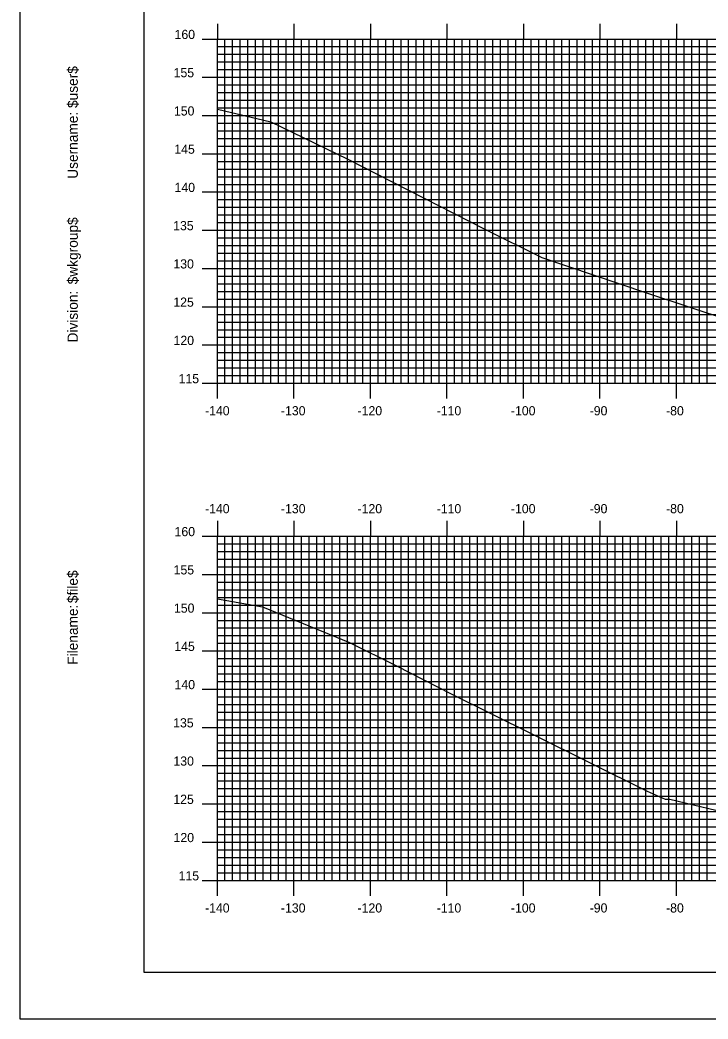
# Model space of a CAD drawing. Extents: x 851533 to 851876, y 366605 to 366825.
# Drawn here: x 851532.7 to 851622.6, y 366604.9 to 366735.5 of the extents above; entities that cross this region are included whole.
import ezdxf

# ---------------------------------------------------------------- set-up
doc = ezdxf.new("R2010")
doc.units = 0
for name, color, linetype in [('BORDER', 7, 'Continuous'), ('H_V ANNOTATION', 7, 'Continuous'), ('MAJOR', 7, 'Continuous'), ('MINOR', 7, 'Continuous'), ('PLOT BOUNDARY', 7, 'Continuous'), ('S_Roadway_Centerline', 7, 'Continuous')]:
    doc.layers.add(name, color=color, linetype=linetype)

msp = doc.modelspace()

# ---------------------------------------------------------------- linework, layer by layer
at = {"layer": 'BORDER'}
msp.add_lwpolyline([(851548.85, 366611.06), (851868.85, 366611.06), (851868.85, 366821.06), (851548.85, 366821.06)], close=True, dxfattribs=at)
at = {"layer": 'MAJOR'}
for p, q in [((851558.45, 366735.06), (851558.45, 366733.06)), ((851568.45, 366735.06), (851568.45, 366733.06)), ((851578.45, 366735.06), (851578.45, 366733.06)), ((851588.45, 366735.06), (851588.45, 366733.06)), ((851598.45, 366735.06), (851598.45, 366733.06)), ((851608.45, 366735.06), (851608.45, 366733.06)), ((851618.45, 366735.06), (851618.45, 366733.06)), ((851556.45, 366733.06), (851558.45, 366733.06)), ((851558.45, 366733.06), (851838.45, 366733.06)), ((851558.45, 366688.06), (851558.45, 366733.06)), ((851558.45, 366688.06), (851558.45, 366733.06)), ((851558.45, 366733.06), (851838.45, 366733.06)), ((851568.45, 366688.06), (851568.45, 366733.06)), ((851578.45, 366688.06), (851578.45, 366733.06)), ((851588.45, 366688.06), (851588.45, 366733.06)), ((851598.45, 366688.06), (851598.45, 366733.06)), ((851608.45, 366688.06), (851608.45, 366733.06)), ((851618.45, 366688.06), (851618.45, 366733.06)), ((851556.45, 366728.06), (851558.45, 366728.06)), ((851558.45, 366728.06), (851838.45, 366728.06)), ((851556.45, 366723.06), (851558.45, 366723.06)), ((851558.45, 366723.06), (851838.45, 366723.06)), ((851556.45, 366718.06), (851558.45, 366718.06)), ((851558.45, 366718.06), (851838.45, 366718.06)), ((851556.45, 366713.06), (851558.45, 366713.06)), ((851558.45, 366713.06), (851838.45, 366713.06)), ((851556.45, 366708.06), (851558.45, 366708.06)), ((851558.45, 366708.06), (851838.45, 366708.06)), ((851556.45, 366703.06), (851558.45, 366703.06)), ((851558.45, 366703.06), (851838.45, 366703.06)), ((851556.45, 366698.06), (851558.45, 366698.06)), ((851558.45, 366698.06), (851838.45, 366698.06)), ((851556.45, 366693.06), (851558.45, 366693.06)), ((851558.45, 366693.06), (851838.45, 366693.06)), ((851556.45, 366688.06), (851558.45, 366688.06)), ((851558.45, 366688.06), (851838.45, 366688.06)), ((851558.45, 366688.06), (851838.45, 366688.06)), ((851558.45, 366686.05), (851558.45, 366688.06)), ((851568.45, 366686.05), (851568.45, 366688.06)), ((851578.45, 366686.05), (851578.45, 366688.06)), ((851588.45, 366686.05), (851588.45, 366688.06)), ((851598.45, 366686.05), (851598.45, 366688.06)), ((851608.45, 366686.05), (851608.45, 366688.06)), ((851618.45, 366686.05), (851618.45, 366688.06)), ((851558.45, 366670.06), (851558.45, 366668.06)), ((851568.45, 366670.06), (851568.45, 366668.06)), ((851578.45, 366670.06), (851578.45, 366668.06)), ((851588.45, 366670.06), (851588.45, 366668.06)), ((851598.45, 366670.06), (851598.45, 366668.06)), ((851608.45, 366670.06), (851608.45, 366668.06)), ((851618.45, 366670.06), (851618.45, 366668.06)), ((851556.45, 366668.06), (851558.45, 366668.06)), ((851558.45, 366668.06), (851838.45, 366668.06)), ((851558.45, 366623.06), (851558.45, 366668.06)), ((851558.45, 366623.06), (851558.45, 366668.06)), ((851558.45, 366668.06), (851838.45, 366668.06)), ((851568.45, 366623.06), (851568.45, 366668.06)), ((851578.45, 366623.06), (851578.45, 366668.06)), ((851588.45, 366623.06), (851588.45, 366668.06)), ((851598.45, 366623.06), (851598.45, 366668.06)), ((851608.45, 366623.06), (851608.45, 366668.06)), ((851618.45, 366623.06), (851618.45, 366668.06)), ((851556.45, 366663.06), (851558.45, 366663.06)), ((851558.45, 366663.06), (851838.45, 366663.06)), ((851556.45, 366658.06), (851558.45, 366658.06)), ((851558.45, 366658.06), (851838.45, 366658.06)), ((851556.45, 366653.06), (851558.45, 366653.06)), ((851558.45, 366653.06), (851838.45, 366653.06)), ((851556.45, 366648.06), (851558.45, 366648.06)), ((851558.45, 366648.06), (851838.45, 366648.06)), ((851556.45, 366643.06), (851558.45, 366643.06)), ((851558.45, 366643.06), (851838.45, 366643.06)), ((851556.45, 366638.06), (851558.45, 366638.06)), ((851558.45, 366638.06), (851838.45, 366638.06)), ((851556.45, 366633.06), (851558.45, 366633.06)), ((851558.45, 366633.06), (851838.45, 366633.06)), ((851556.45, 366628.06), (851558.45, 366628.06)), ((851558.45, 366628.06), (851838.45, 366628.06)), ((851556.45, 366623.06), (851558.45, 366623.06)), ((851558.45, 366623.06), (851838.45, 366623.06)), ((851558.45, 366623.06), (851838.45, 366623.06)), ((851558.45, 366621.05), (851558.45, 366623.06)), ((851568.45, 366621.05), (851568.45, 366623.06)), ((851578.45, 366621.05), (851578.45, 366623.06)), ((851588.45, 366621.05), (851588.45, 366623.06)), ((851598.45, 366621.05), (851598.45, 366623.06)), ((851608.45, 366621.05), (851608.45, 366623.06)), ((851618.45, 366621.05), (851618.45, 366623.06))]:
    msp.add_line(p, q, dxfattribs=at)
at = {"layer": 'MINOR'}
for p, q in [((851559.45, 366688.06), (851559.45, 366733.06)), ((851560.45, 366688.06), (851560.45, 366733.06)), ((851561.45, 366688.06), (851561.45, 366733.06)), ((851562.45, 366688.06), (851562.45, 366733.06)), ((851563.45, 366688.06), (851563.45, 366733.06)), ((851564.45, 366688.06), (851564.45, 366733.06)), ((851565.45, 366688.06), (851565.45, 366733.06)), ((851566.45, 366688.06), (851566.45, 366733.06)), ((851567.45, 366688.06), (851567.45, 366733.06)), ((851569.45, 366688.06), (851569.45, 366733.06)), ((851570.45, 366688.06), (851570.45, 366733.06)), ((851571.45, 366688.06), (851571.45, 366733.06)), ((851572.45, 366688.06), (851572.45, 366733.06)), ((851573.45, 366688.06), (851573.45, 366733.06)), ((851574.45, 366688.06), (851574.45, 366733.06)), ((851575.45, 366688.06), (851575.45, 366733.06)), ((851576.45, 366688.06), (851576.45, 366733.06)), ((851577.45, 366688.06), (851577.45, 366733.06)), ((851579.45, 366688.06), (851579.45, 366733.06)), ((851580.45, 366688.06), (851580.45, 366733.06)), ((851581.45, 366688.06), (851581.45, 366733.06)), ((851582.45, 366688.06), (851582.45, 366733.06)), ((851583.45, 366688.06), (851583.45, 366733.06)), ((851584.45, 366688.06), (851584.45, 366733.06)), ((851585.45, 366688.06), (851585.45, 366733.06)), ((851586.45, 366688.06), (851586.45, 366733.06)), ((851587.45, 366688.06), (851587.45, 366733.06)), ((851589.45, 366688.06), (851589.45, 366733.06)), ((851590.45, 366688.06), (851590.45, 366733.06)), ((851591.45, 366688.06), (851591.45, 366733.06)), ((851592.45, 366688.06), (851592.45, 366733.06)), ((851593.45, 366688.06), (851593.45, 366733.06)), ((851594.45, 366688.06), (851594.45, 366733.06)), ((851595.45, 366688.06), (851595.45, 366733.06)), ((851596.45, 366688.06), (851596.45, 366733.06)), ((851597.45, 366688.06), (851597.45, 366733.06)), ((851599.45, 366688.06), (851599.45, 366733.06)), ((851600.45, 366688.06), (851600.45, 366733.06)), ((851601.45, 366688.06), (851601.45, 366733.06)), ((851602.45, 366688.06), (851602.45, 366733.06)), ((851603.45, 366688.06), (851603.45, 366733.06)), ((851604.45, 366688.06), (851604.45, 366733.06)), ((851605.45, 366688.06), (851605.45, 366733.06)), ((851606.45, 366688.06), (851606.45, 366733.06)), ((851607.45, 366688.06), (851607.45, 366733.06)), ((851609.45, 366688.06), (851609.45, 366733.06)), ((851610.45, 366688.06), (851610.45, 366733.06)), ((851611.45, 366688.06), (851611.45, 366733.06)), ((851612.45, 366688.06), (851612.45, 366733.06)), ((851613.45, 366688.06), (851613.45, 366733.06)), ((851614.45, 366688.06), (851614.45, 366733.06)), ((851615.45, 366688.06), (851615.45, 366733.06)), ((851616.45, 366688.06), (851616.45, 366733.06)), ((851617.45, 366688.06), (851617.45, 366733.06)), ((851619.45, 366688.06), (851619.45, 366733.06)), ((851620.45, 366688.06), (851620.45, 366733.06)), ((851621.45, 366688.06), (851621.45, 366733.06)), ((851622.45, 366688.06), (851622.45, 366733.06)), ((851558.45, 366732.06), (851838.45, 366732.06)), ((851558.45, 366732.06), (851560.46, 366732.06)), ((851558.45, 366731.06), (851838.45, 366731.06)), ((851558.45, 366731.06), (851560.46, 366731.06)), ((851558.45, 366730.06), (851838.45, 366730.06)), ((851558.45, 366730.06), (851560.46, 366730.06)), ((851558.45, 366729.06), (851838.45, 366729.06)), ((851558.45, 366729.06), (851560.46, 366729.06)), ((851558.45, 366727.06), (851838.45, 366727.06)), ((851558.45, 366727.06), (851560.46, 366727.06)), ((851558.45, 366726.06), (851838.45, 366726.06)), ((851558.45, 366726.06), (851560.46, 366726.06)), ((851558.45, 366725.06), (851838.45, 366725.06)), ((851558.45, 366725.06), (851560.46, 366725.06)), ((851558.45, 366724.06), (851838.45, 366724.06)), ((851558.45, 366724.06), (851560.46, 366724.06)), ((851558.45, 366722.06), (851838.45, 366722.06)), ((851558.45, 366722.06), (851560.46, 366722.06)), ((851558.45, 366721.06), (851838.45, 366721.06)), ((851558.45, 366721.06), (851560.46, 366721.06)), ((851558.45, 366720.06), (851838.45, 366720.06)), ((851558.45, 366720.06), (851560.46, 366720.06)), ((851558.45, 366719.06), (851838.45, 366719.06)), ((851558.45, 366719.06), (851560.46, 366719.06)), ((851558.45, 366717.06), (851838.45, 366717.06)), ((851558.45, 366717.06), (851560.46, 366717.06)), ((851558.45, 366716.06), (851838.45, 366716.06)), ((851558.45, 366716.06), (851560.46, 366716.06)), ((851558.45, 366715.06), (851838.45, 366715.06)), ((851558.45, 366715.06), (851560.46, 366715.06)), ((851558.45, 366714.06), (851838.45, 366714.06)), ((851558.45, 366714.06), (851560.46, 366714.06)), ((851558.45, 366712.06), (851838.45, 366712.06)), ((851558.45, 366712.06), (851560.46, 366712.06)), ((851558.45, 366711.06), (851838.45, 366711.06)), ((851558.45, 366711.06), (851560.46, 366711.06)), ((851558.45, 366710.06), (851838.45, 366710.06)), ((851558.45, 366710.06), (851560.46, 366710.06)), ((851558.45, 366709.06), (851838.45, 366709.06)), ((851558.45, 366709.06), (851560.46, 366709.06)), ((851558.45, 366707.06), (851838.45, 366707.06)), ((851558.45, 366707.06), (851560.46, 366707.06)), ((851558.45, 366706.06), (851838.45, 366706.06)), ((851558.45, 366706.06), (851560.46, 366706.06)), ((851558.45, 366705.06), (851838.45, 366705.06)), ((851558.45, 366705.06), (851560.46, 366705.06)), ((851558.45, 366704.06), (851838.45, 366704.06)), ((851558.45, 366704.06), (851560.46, 366704.06)), ((851558.45, 366702.06), (851838.45, 366702.06)), ((851558.45, 366702.06), (851560.46, 366702.06)), ((851558.45, 366701.06), (851838.45, 366701.06)), ((851558.45, 366701.06), (851560.46, 366701.06)), ((851558.45, 366700.06), (851838.45, 366700.06)), ((851558.45, 366700.06), (851560.46, 366700.06)), ((851558.45, 366699.06), (851838.45, 366699.06)), ((851558.45, 366699.06), (851560.46, 366699.06)), ((851558.45, 366697.06), (851838.45, 366697.06)), ((851558.45, 366697.06), (851560.46, 366697.06)), ((851558.45, 366696.06), (851838.45, 366696.06)), ((851558.45, 366696.06), (851560.46, 366696.06)), ((851558.45, 366695.06), (851838.45, 366695.06)), ((851558.45, 366695.06), (851560.46, 366695.06)), ((851558.45, 366694.06), (851838.45, 366694.06)), ((851558.45, 366694.06), (851560.46, 366694.06)), ((851558.45, 366692.06), (851838.45, 366692.06)), ((851558.45, 366692.06), (851560.46, 366692.06)), ((851558.45, 366691.06), (851838.45, 366691.06)), ((851558.45, 366691.06), (851560.46, 366691.06)), ((851558.45, 366690.06), (851838.45, 366690.06)), ((851558.45, 366690.06), (851560.46, 366690.06)), ((851558.45, 366689.06), (851838.45, 366689.06)), ((851558.45, 366689.06), (851560.46, 366689.06)), ((851559.45, 366623.06), (851559.45, 366668.06)), ((851560.45, 366623.06), (851560.45, 366668.06)), ((851561.45, 366623.06), (851561.45, 366668.06)), ((851562.45, 366623.06), (851562.45, 366668.06)), ((851563.45, 366623.06), (851563.45, 366668.06)), ((851564.45, 366623.06), (851564.45, 366668.06)), ((851565.45, 366623.06), (851565.45, 366668.06)), ((851566.45, 366623.06), (851566.45, 366668.06)), ((851567.45, 366623.06), (851567.45, 366668.06)), ((851569.45, 366623.06), (851569.45, 366668.06)), ((851570.45, 366623.06), (851570.45, 366668.06)), ((851571.45, 366623.06), (851571.45, 366668.06)), ((851572.45, 366623.06), (851572.45, 366668.06)), ((851573.45, 366623.06), (851573.45, 366668.06)), ((851574.45, 366623.06), (851574.45, 366668.06)), ((851575.45, 366623.06), (851575.45, 366668.06)), ((851576.45, 366623.06), (851576.45, 366668.06)), ((851577.45, 366623.06), (851577.45, 366668.06)), ((851579.45, 366623.06), (851579.45, 366668.06)), ((851580.45, 366623.06), (851580.45, 366668.06)), ((851581.45, 366623.06), (851581.45, 366668.06)), ((851582.45, 366623.06), (851582.45, 366668.06)), ((851583.45, 366623.06), (851583.45, 366668.06)), ((851584.45, 366623.06), (851584.45, 366668.06)), ((851585.45, 366623.06), (851585.45, 366668.06)), ((851586.45, 366623.06), (851586.45, 366668.06)), ((851587.45, 366623.06), (851587.45, 366668.06)), ((851589.45, 366623.06), (851589.45, 366668.06)), ((851590.45, 366623.06), (851590.45, 366668.06)), ((851591.45, 366623.06), (851591.45, 366668.06)), ((851592.45, 366623.06), (851592.45, 366668.06)), ((851593.45, 366623.06), (851593.45, 366668.06)), ((851594.45, 366623.06), (851594.45, 366668.06)), ((851595.45, 366623.06), (851595.45, 366668.06)), ((851596.45, 366623.06), (851596.45, 366668.06)), ((851597.45, 366623.06), (851597.45, 366668.06)), ((851599.45, 366623.06), (851599.45, 366668.06)), ((851600.45, 366623.06), (851600.45, 366668.06)), ((851601.45, 366623.06), (851601.45, 366668.06)), ((851602.45, 366623.06), (851602.45, 366668.06)), ((851603.45, 366623.06), (851603.45, 366668.06)), ((851604.45, 366623.06), (851604.45, 366668.06)), ((851605.45, 366623.06), (851605.45, 366668.06)), ((851606.45, 366623.06), (851606.45, 366668.06)), ((851607.45, 366623.06), (851607.45, 366668.06)), ((851609.45, 366623.06), (851609.45, 366668.06)), ((851610.45, 366623.06), (851610.45, 366668.06)), ((851611.45, 366623.06), (851611.45, 366668.06)), ((851612.45, 366623.06), (851612.45, 366668.06)), ((851613.45, 366623.06), (851613.45, 366668.06)), ((851614.45, 366623.06), (851614.45, 366668.06)), ((851615.45, 366623.06), (851615.45, 366668.06)), ((851616.45, 366623.06), (851616.45, 366668.06)), ((851617.45, 366623.06), (851617.45, 366668.06)), ((851619.45, 366623.06), (851619.45, 366668.06)), ((851620.45, 366623.06), (851620.45, 366668.06)), ((851621.45, 366623.06), (851621.45, 366668.06)), ((851622.45, 366623.06), (851622.45, 366668.06)), ((851558.45, 366667.06), (851838.45, 366667.06)), ((851558.45, 366667.06), (851560.46, 366667.06)), ((851558.45, 366666.06), (851838.45, 366666.06)), ((851558.45, 366666.06), (851560.46, 366666.06)), ((851558.45, 366665.06), (851838.45, 366665.06)), ((851558.45, 366665.06), (851560.46, 366665.06)), ((851558.45, 366664.06), (851838.45, 366664.06)), ((851558.45, 366664.06), (851560.46, 366664.06)), ((851558.45, 366662.06), (851838.45, 366662.06)), ((851558.45, 366662.06), (851560.46, 366662.06)), ((851558.45, 366661.06), (851838.45, 366661.06)), ((851558.45, 366661.06), (851560.46, 366661.06)), ((851558.45, 366660.06), (851838.45, 366660.06)), ((851558.45, 366660.06), (851560.46, 366660.06)), ((851558.45, 366659.06), (851838.45, 366659.06)), ((851558.45, 366659.06), (851560.46, 366659.06)), ((851558.45, 366657.06), (851838.45, 366657.06)), ((851558.45, 366657.06), (851560.46, 366657.06)), ((851558.45, 366656.06), (851838.45, 366656.06)), ((851558.45, 366656.06), (851560.46, 366656.06)), ((851558.45, 366655.06), (851838.45, 366655.06)), ((851558.45, 366655.06), (851560.46, 366655.06)), ((851558.45, 366654.06), (851838.45, 366654.06)), ((851558.45, 366654.06), (851560.46, 366654.06)), ((851558.45, 366652.06), (851838.45, 366652.06)), ((851558.45, 366652.06), (851560.46, 366652.06)), ((851558.45, 366651.06), (851838.45, 366651.06)), ((851558.45, 366651.06), (851560.46, 366651.06)), ((851558.45, 366650.06), (851838.45, 366650.06)), ((851558.45, 366650.06), (851560.46, 366650.06)), ((851558.45, 366649.06), (851838.45, 366649.06)), ((851558.45, 366649.06), (851560.46, 366649.06)), ((851558.45, 366647.06), (851838.45, 366647.06)), ((851558.45, 366647.06), (851560.46, 366647.06)), ((851558.45, 366646.06), (851838.45, 366646.06)), ((851558.45, 366646.06), (851560.46, 366646.06)), ((851558.45, 366645.06), (851838.45, 366645.06)), ((851558.45, 366645.06), (851560.46, 366645.06)), ((851558.45, 366644.06), (851838.45, 366644.06)), ((851558.45, 366644.06), (851560.46, 366644.06)), ((851558.45, 366642.06), (851838.45, 366642.06)), ((851558.45, 366642.06), (851560.46, 366642.06)), ((851558.45, 366641.06), (851838.45, 366641.06)), ((851558.45, 366641.06), (851560.46, 366641.06)), ((851558.45, 366640.06), (851838.45, 366640.06)), ((851558.45, 366640.06), (851560.46, 366640.06)), ((851558.45, 366639.06), (851838.45, 366639.06)), ((851558.45, 366639.06), (851560.46, 366639.06)), ((851558.45, 366637.06), (851838.45, 366637.06)), ((851558.45, 366637.06), (851560.46, 366637.06)), ((851558.45, 366636.06), (851838.45, 366636.06)), ((851558.45, 366636.06), (851560.46, 366636.06)), ((851558.45, 366635.06), (851838.45, 366635.06)), ((851558.45, 366635.06), (851560.46, 366635.06)), ((851558.45, 366634.06), (851838.45, 366634.06)), ((851558.45, 366634.06), (851560.46, 366634.06)), ((851558.45, 366632.06), (851838.45, 366632.06)), ((851558.45, 366632.06), (851560.46, 366632.06)), ((851558.45, 366631.06), (851838.45, 366631.06)), ((851558.45, 366631.06), (851560.46, 366631.06)), ((851558.45, 366630.06), (851838.45, 366630.06)), ((851558.45, 366630.06), (851560.46, 366630.06)), ((851558.45, 366629.06), (851838.45, 366629.06)), ((851558.45, 366629.06), (851560.46, 366629.06)), ((851558.45, 366627.06), (851838.45, 366627.06)), ((851558.45, 366627.06), (851560.46, 366627.06)), ((851558.45, 366626.06), (851838.45, 366626.06)), ((851558.45, 366626.06), (851560.46, 366626.06)), ((851558.45, 366625.06), (851838.45, 366625.06)), ((851558.45, 366625.06), (851560.46, 366625.06)), ((851558.45, 366624.06), (851838.45, 366624.06)), ((851558.45, 366624.06), (851560.46, 366624.06))]:
    msp.add_line(p, q, dxfattribs=at)
at = {"layer": 'PLOT BOUNDARY'}
msp.add_lwpolyline([(851532.66, 366604.94), (851872.66, 366604.94), (851872.66, 366824.94), (851532.66, 366824.94)], close=True, dxfattribs=at)
at = {"layer": 'S_Roadway_Centerline'}
for points in [[(851558.45, 366723.88), (851565.46, 366722.22), (851575.41, 366717.38), (851593.31, 366708.23), (851600.87, 366704.51), (851614.52, 366699.89), (851625.46, 366696.27)], [(851558.45, 366659.87), (851564.36, 366658.81), (851575.74, 366654.18), (851581.86, 366651.1), (851588.99, 366647.43), (851599.65, 366642.17), (851614.6, 366634.72), (851616.97, 366633.66), (851617.56, 366633.69), (851626.69, 366631.52)]]:
    msp.add_lwpolyline(points, dxfattribs=at)

# ---------------------------------------------------------------- texts
at = {"layer": 'BORDER'}
for s, p in [('$user$', (851540.22, 366724.04)), ('Username:', (851540.22, 366714.79)), ('$wkgroup$', (851540.22, 366700.99)), ('Division:', (851540.22, 366693.39)), ('$file$', (851540.22, 366659.31)), ('Filename:', (851540.22, 366651.25))]:
    msp.add_text(s, height=1.339, rotation=90, dxfattribs=at).set_placement(p)
at = {"layer": 'H_V ANNOTATION'}
for s, p in [('160', (851552.86, 366733.06)), ('155', (851552.74, 366728.06)), ('150', (851552.78, 366723.06)), ('145', (851552.83, 366718.06)), ('140', (851552.86, 366713.06)), ('135', (851552.68, 366708.06)), ('130', (851552.71, 366703.06)), ('125', (851552.7, 366698.06)), ('120', (851552.73, 366693.06)), ('115', (851553.39, 366688.06)), ('-140', (851556.84, 366683.86)), ('-130', (851566.76, 366683.86)), ('-120', (851576.77, 366683.86)), ('-110', (851587.11, 366683.86)), ('-100', (851596.81, 366683.86)), ('-90', (851607.1, 366683.86)), ('-80', (851617.08, 366683.86)), ('-140', (851556.84, 366671.06)), ('-130', (851566.76, 366671.06)), ('-120', (851576.77, 366671.06)), ('-110', (851587.11, 366671.06)), ('-100', (851596.81, 366671.06)), ('-90', (851607.1, 366671.06)), ('-80', (851617.08, 366671.06)), ('160', (851552.86, 366668.06)), ('155', (851552.74, 366663.06)), ('150', (851552.78, 366658.06)), ('145', (851552.83, 366653.06)), ('140', (851552.86, 366648.06)), ('135', (851552.68, 366643.06)), ('130', (851552.71, 366638.06)), ('125', (851552.7, 366633.06)), ('120', (851552.73, 366628.06)), ('115', (851553.39, 366623.06)), ('-140', (851556.84, 366618.86)), ('-130', (851566.76, 366618.86)), ('-120', (851576.77, 366618.86)), ('-110', (851587.11, 366618.86)), ('-100', (851596.81, 366618.86)), ('-90', (851607.1, 366618.86)), ('-80', (851617.08, 366618.86))]:
    msp.add_text(s, height=1.2, dxfattribs=at).set_placement(p)
at = {"layer": 'MAJOR'}
for p in [(851558.44, 366688.06), (851558.44, 366623.06)]:
    msp.add_text('-', height=0.012, dxfattribs=at).set_placement(p)

doc.saveas('drawing.dxf')
